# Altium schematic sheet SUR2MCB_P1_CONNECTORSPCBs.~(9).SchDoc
size 420 x 297 mm; Scale: 1:1; Разраб.: Иванов; Обозначение документа: АБВГ.123456.001 Э3; Пров.: Петров; Утв.: Сидоров; Наименование организации: ОАО "Концерн "МПО-Гидроприбор"; Перв. применение: АБВГ.123456.000; Наименование изделия 1: Плата; Наименование изделия 2: Схема электрическая; Наименование изделия 3: принципиальная; Нач. отд.: Нач. отд.; Фамилия нач. отд.: Сидоров
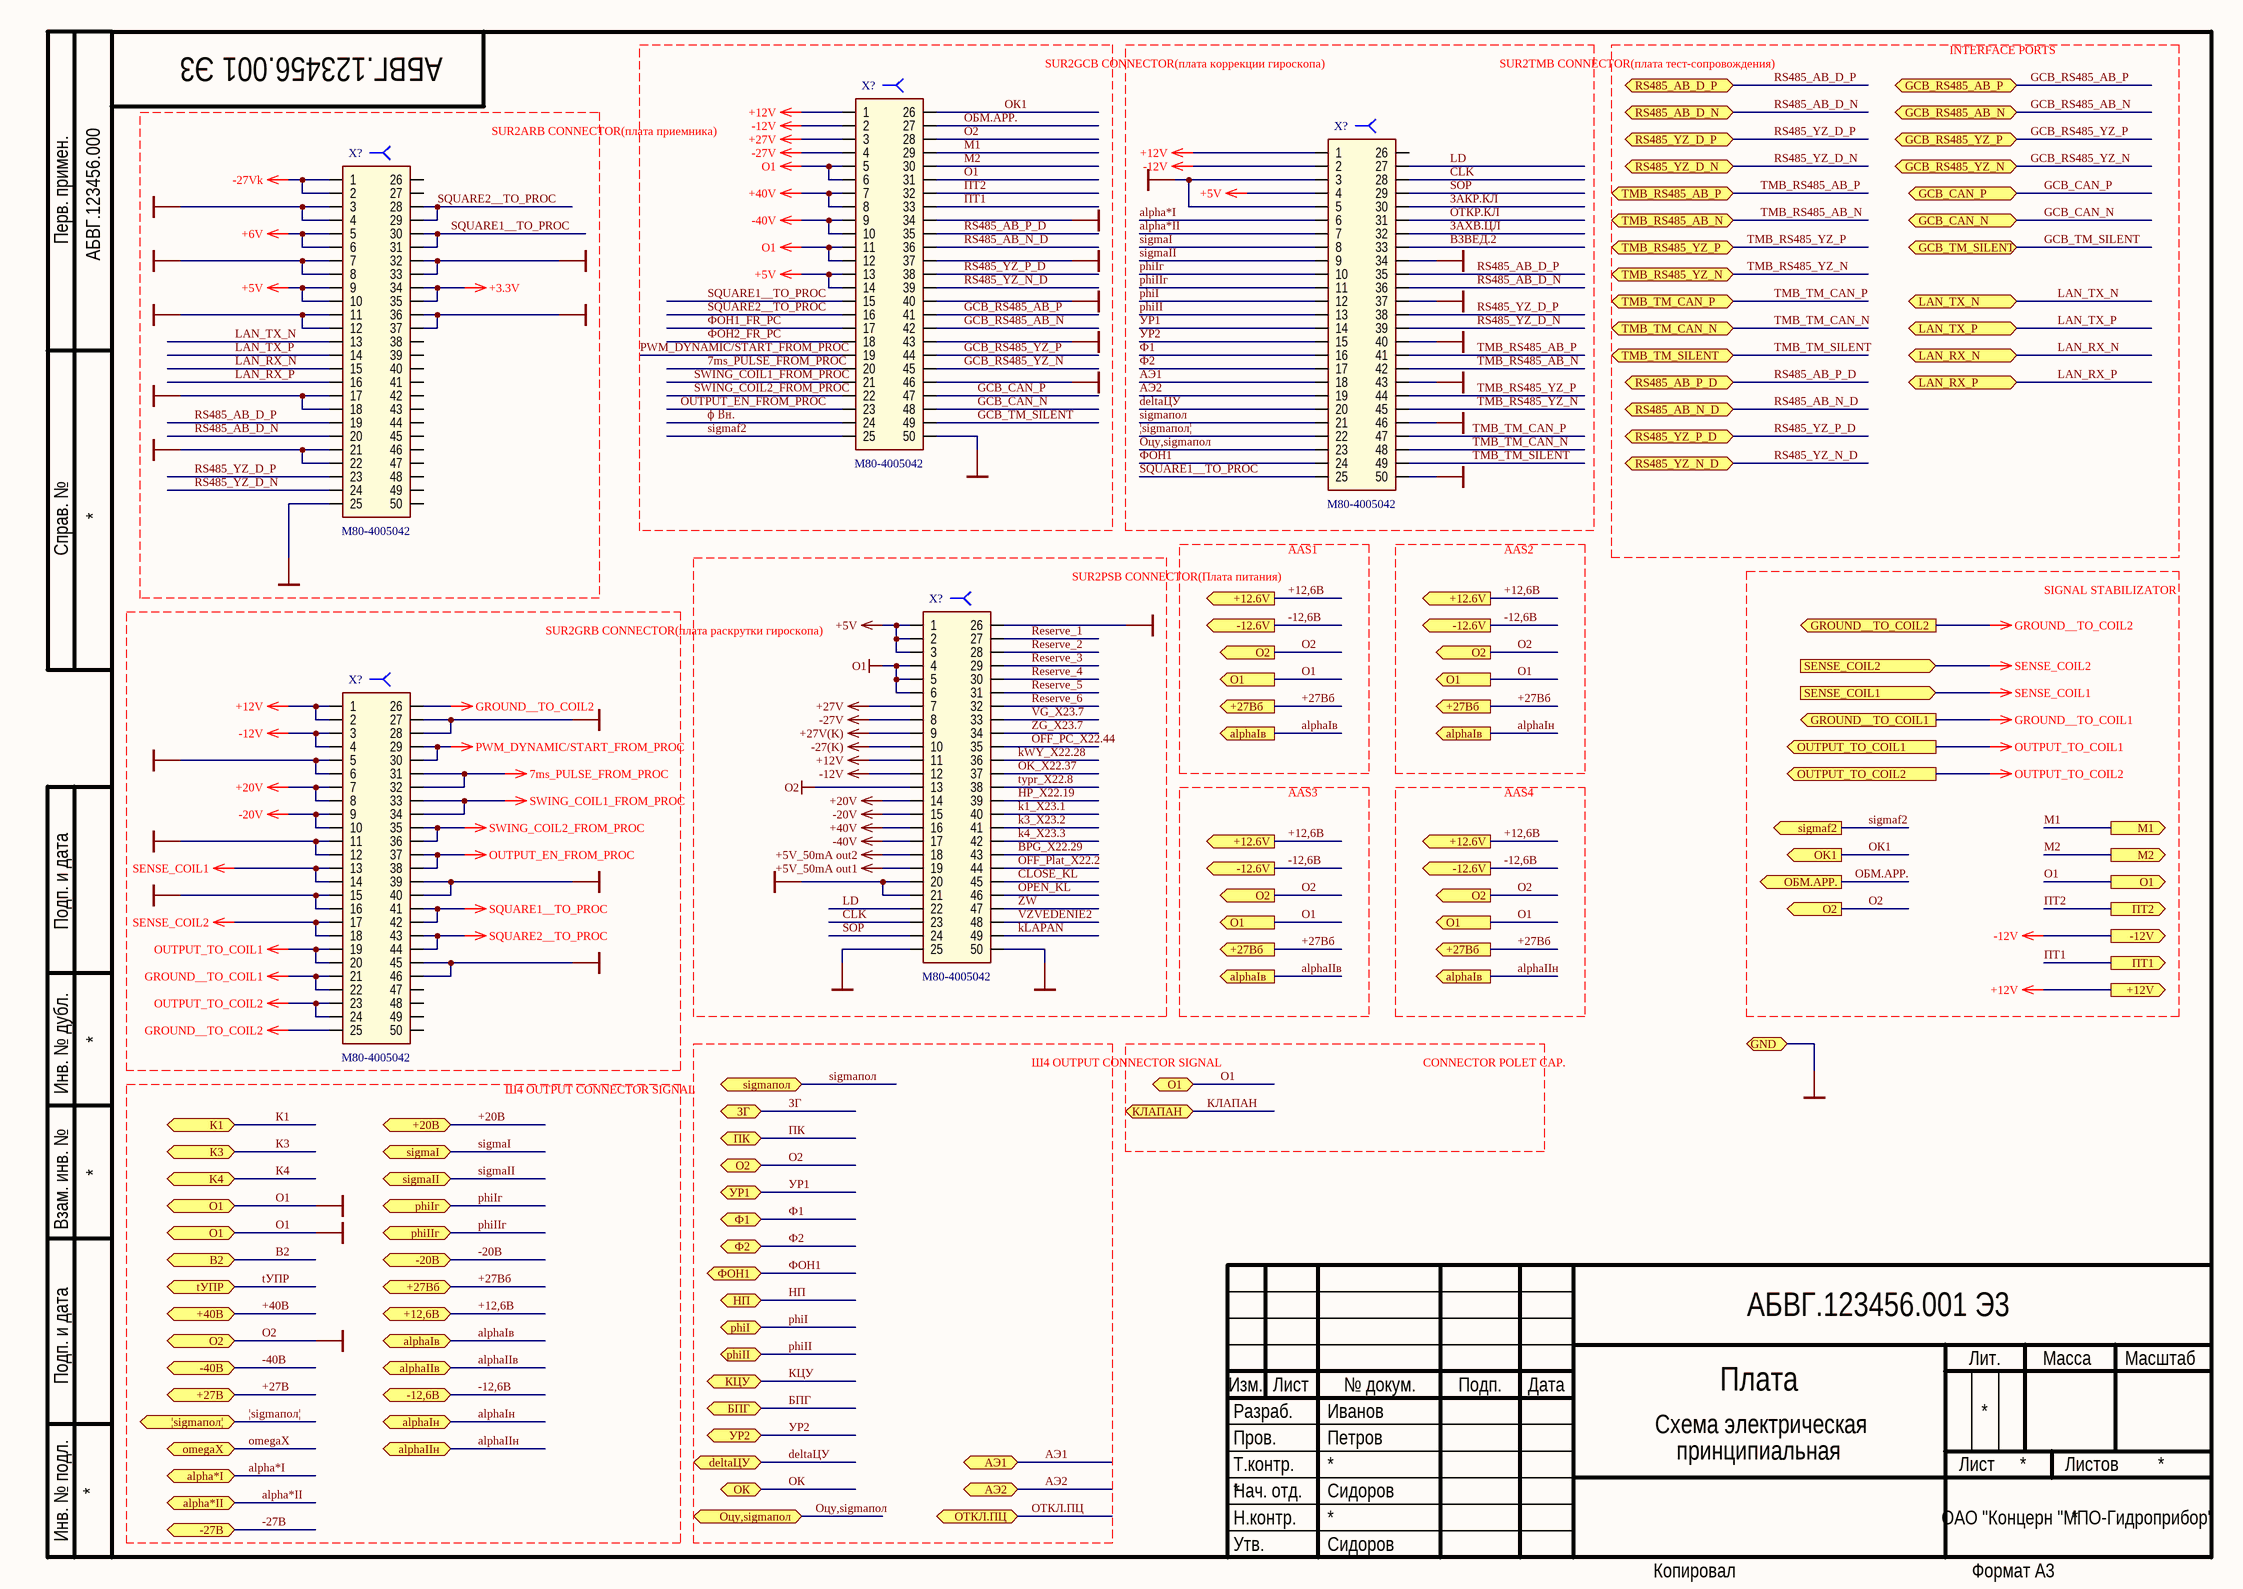
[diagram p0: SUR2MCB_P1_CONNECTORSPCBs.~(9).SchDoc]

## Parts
(Parts that share a designator on the sheet are numbered #1, #2 ... from top to bottom, then left to right.)
X?#1  value M80-4005042  [M80-4005042]
X?#2  value M80-4005042  [M80-4005042]
X?#3  value M80-4005042  [M80-4005042]
X?#4  value M80-4005042  [M80-4005042]
X?#5  value M80-4005042  [M80-4005042]

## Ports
+12,6В (bidir), +12.6V (out), +12V (out), +20В (bidir), +27В (bidir), +27Вб (bidir), +27Вб (out), +40В (bidir), -12,6В (bidir), -12.6V (out), -12V (out), -20В (bidir), -27В (bidir), -40В (bidir), alpha*I (bidir), alpha*II (bidir), alphaIIв (bidir), alphaIIн (bidir), alphaIв (bidir), alphaIв (out), alphaIн (bidir), B2 (bidir), deltaЦУ (bidir), GCB_CAN_N (bidir), GCB_CAN_P (bidir), GCB_RS485_AB_N (bidir), GCB_RS485_AB_P (bidir), GCB_RS485_YZ_N (bidir), GCB_RS485_YZ_P (bidir), GCB_TM_SILENT (bidir), GND (bidir), GROUND__TO_COIL1 (out), GROUND__TO_COIL2 (out), K4 (bidir), LAN_RX_N (bidir), LAN_RX_P (bidir), LAN_TX_N (bidir), LAN_TX_P (bidir), M1 (out), M2 (out), O1 (bidir), O1 (out), O2 (bidir), O2 (out), OK1 (out), omegaX (bidir), OUTPUT_TO_COIL1 (out), OUTPUT_TO_COIL2 (out), phiI (bidir), phiII (bidir), phiIIг (bidir), phiIг (bidir), RS485_AB_D_N (bidir), RS485_AB_D_P (bidir), RS485_AB_N_D (bidir), RS485_AB_P_D (bidir), RS485_YZ_D_N (bidir), RS485_YZ_D_P (bidir), RS485_YZ_N_D (bidir), RS485_YZ_P_D (bidir), SENSE_COIL1 (in), SENSE_COIL2 (in), sigmaf2 (out), sigmaI (bidir), sigmaII (bidir), sigmaпол (bidir), TMB_RS485_AB_N (bidir), TMB_RS485_AB_P (bidir), TMB_RS485_YZ_N (bidir), TMB_RS485_YZ_P (bidir), TMB_TM_CAN_N (bidir), TMB_TM_CAN_P (bidir), TMB_TM_SILENT (bidir), tУПР (bidir), ¦sigmaпол¦ (bidir), АЭ1 (bidir), АЭ2 (bidir), БПГ (bidir), ЗГ (bidir), К1 (bidir), К3 (bidir), КЛАПАН (bidir), КЦУ (bidir), НП (bidir), О1 (bidir), О2 (bidir), ОБМ.АРР. (out), ОК (bidir), ОТКЛ.ПЦ (bidir), Оцу,sigmaпол (bidir), ПК (bidir), ПТ1 (out), ПТ2 (out), УР1 (bidir), УР2 (bidir), Ф1 (bidir), Ф2 (bidir), ФОН1 (bidir)

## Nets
7ms_PULSE_FROM_PROC: X?#1.20 X?#5.31 X?#5.32
+3.3V: X?#3.34 X?#3.35
+5V: X?#1.13 X?#1.14 X?#2.4 X?#3.9 X?#3.10 X?#4.1 X?#4.2 X?#4.3
+5V_50mA out1: X?#4.19
+5V_50mA out2: X?#4.18
+6V: X?#3.5 X?#3.6
+12V: X?#1.1 X?#2.1 X?#4.11 X?#5.1 X?#5.2 ; port +12V
+20V: X?#4.14 X?#5.7 X?#5.8
+27V: X?#1.3 X?#4.7
+27V(K): X?#4.9
+40V: X?#1.7 X?#1.8 X?#4.16
-12V: X?#1.2 X?#2.2 X?#4.12 X?#5.3 X?#5.4 ; port -12V
-20V: X?#4.15 X?#5.9 X?#5.10
-27(K): X?#4.10
-27V: X?#1.4 X?#4.8
-27Vk: X?#3.1 X?#3.2
-40V: X?#1.9 X?#1.10 X?#4.17
GROUND__TO_COIL1: X?#5.21 X?#5.22 ; port GROUND__TO_COIL1
GROUND__TO_COIL2: X?#5.25 X?#5.26 ; port GROUND__TO_COIL2
OUTPUT_EN_FROM_PROC: X?#1.23 X?#5.37 X?#5.38
OUTPUT_TO_COIL1: X?#5.19 X?#5.20 ; port OUTPUT_TO_COIL1
OUTPUT_TO_COIL2: X?#5.23 X?#5.24 ; port OUTPUT_TO_COIL2
PWM_DYNAMIC/START_FROM_PROC: X?#1.19 X?#5.29 X?#5.30
SENSE_COIL1: X?#5.13 X?#5.14 ; port SENSE_COIL1
SENSE_COIL2: X?#5.17 X?#5.18 ; port SENSE_COIL2
SQUARE1__TO_PROC: X?#1.15 X?#2.25 X?#3.30 X?#3.31 X?#5.41 X?#5.42
SQUARE2__TO_PROC: X?#1.16 X?#3.28 X?#3.29 X?#5.43 X?#5.44
SWING_COIL1_FROM_PROC: X?#1.21 X?#5.33 X?#5.34
SWING_COIL2_FROM_PROC: X?#1.22 X?#5.35 X?#5.36
О1: X?#1.5 X?#1.6 X?#1.11 X?#1.12 X?#1.28 X?#1.31 X?#1.34 X?#1.37 X?#1.40 X?#1.43 X?#1.46 X?#1.50 X?#2.3 X?#2.5 X?#2.34 X?#2.37 X?#2.40 X?#2.43 X?#2.46 X?#2.50 X?#3.3 X?#3.4 X?#3.7 X?#3.8 X?#3.11 X?#3.12 X?#3.17 X?#3.18 X?#3.21 X?#3.22 X?#3.25 X?#3.32 X?#3.33 X?#3.36 X?#3.37 X?#4.4 X?#4.5 X?#4.6 X?#4.13 X?#4.20 X?#4.21 X?#4.25 X?#4.26 X?#4.50 X?#5.5 X?#5.6 X?#5.11 X?#5.12 X?#5.15 X?#5.16 X?#5.27 X?#5.28 X?#5.39 X?#5.40 X?#5.45 X?#5.46 ; port O1, port O2, port О2, port О1, port GND  [also labelled GND, О2]
+12,6В: port +12.6V, port +12,6В
-12,6В: port -12.6V, port -12,6В
alpha*I: X?#2.6 ; port alpha*I
alpha*II: X?#2.7 ; port alpha*II
alphaIIв: port alphaIв, port alphaIIв, port alphaIн, port alphaIIн  [also labelled alphaIIн, alphaIв, alphaIн]
BPG_X22.29: X?#4.43
CLK: X?#2.28 X?#4.23
CLOSE_KL: X?#4.45
deltaЦУ: X?#2.20 ; port deltaЦУ
GCB_CAN_N: X?#1.48 ; port GCB_CAN_N
GCB_CAN_P: X?#1.47 ; port GCB_CAN_P
GCB_RS485_AB_N: X?#1.42 ; port GCB_RS485_AB_N
GCB_RS485_AB_P: X?#1.41 ; port GCB_RS485_AB_P
GCB_RS485_YZ_N: X?#1.45 ; port GCB_RS485_YZ_N
GCB_RS485_YZ_P: X?#1.44 ; port GCB_RS485_YZ_P
GCB_TM_SILENT: X?#1.49 ; port GCB_TM_SILENT
HP_X22.19: X?#4.39
k1_X23.1: X?#4.40
k3_X23.2: X?#4.41
k4_X23.3: X?#4.42
kLAPAN: X?#4.49
kWY_X22.28: X?#4.36
LAN_RX_N: X?#3.15 ; port LAN_RX_N
LAN_RX_P: X?#3.16 ; port LAN_RX_P
LAN_TX_N: X?#3.13 ; port LAN_TX_N
LAN_TX_P: X?#3.14 ; port LAN_TX_P
LD: X?#2.27 X?#4.22
OFF_PC_X22.44: X?#4.35
OFF_Plat_X22.2: X?#4.44
OK_X22.37: X?#4.37
OPEN_KL: X?#4.46
phiI: X?#2.12 ; port phiI
phiII: X?#2.13 ; port phiII
phiIIг: X?#2.11 ; port phiIIг
phiIг: X?#2.10 ; port phiIг
Reserve_1: X?#4.27
Reserve_2: X?#4.28
Reserve_3: X?#4.29
Reserve_4: X?#4.30
Reserve_5: X?#4.31
Reserve_6: X?#4.32
RS485_AB_D_N: X?#2.36 X?#3.20 ; port RS485_AB_D_N
RS485_AB_D_P: X?#2.35 X?#3.19 ; port RS485_AB_D_P
RS485_AB_N_D: X?#1.36 ; port RS485_AB_N_D
RS485_AB_P_D: X?#1.35 ; port RS485_AB_P_D
RS485_YZ_D_N: X?#2.39 X?#3.24 ; port RS485_YZ_D_N
RS485_YZ_D_P: X?#2.38 X?#3.23 ; port RS485_YZ_D_P
RS485_YZ_N_D: X?#1.39 ; port RS485_YZ_N_D
RS485_YZ_P_D: X?#1.38 ; port RS485_YZ_P_D
sigmaf2: X?#1.25 ; port sigmaf2
sigmaI: X?#2.8 ; port sigmaI
sigmaII: X?#2.9 ; port sigmaII
sigmaпол: X?#2.21 ; port sigmaпол
SOP: X?#2.29 X?#4.24
TMB_RS485_AB_N: X?#2.42 ; port TMB_RS485_AB_N
TMB_RS485_AB_P: X?#2.41 ; port TMB_RS485_AB_P
TMB_RS485_YZ_N: X?#2.45 ; port TMB_RS485_YZ_N
TMB_RS485_YZ_P: X?#2.44 ; port TMB_RS485_YZ_P
TMB_TM_CAN_N: X?#2.48 ; port TMB_TM_CAN_N
TMB_TM_CAN_P: X?#2.47 ; port TMB_TM_CAN_P
TMB_TM_SILENT: X?#2.49 ; port TMB_TM_SILENT
typr_X22.8: X?#4.38
VG_X23.7: X?#4.33
VZVEDENIE2: X?#4.48
ZG_X23.7: X?#4.34
ZW: X?#4.47
¦sigmaпол¦: X?#2.22 ; port ¦sigmaпол¦
ϕ Вн.: X?#1.24
АЭ1: X?#2.18 ; port АЭ1
АЭ2: X?#2.19 ; port АЭ2
ВЗВЕД.2: X?#2.33
ЗАКР.КЛ: X?#2.30
ЗАХВ.ЦЛ: X?#2.32
М1: X?#1.29 ; port M1
М2: X?#1.30 ; port M2
ОБМ.АРР.: X?#1.27 ; port ОБМ.АРР.
ОК1: X?#1.26 ; port OK1
ОТКР.КЛ: X?#2.31
Оцу,sigmaпол: X?#2.23 ; port Оцу,sigmaпол
ПТ1: X?#1.33 ; port ПТ1
ПТ2: X?#1.32 ; port ПТ2
УР1: X?#2.14 ; port УР1
УР2: X?#2.15 ; port УР2
Ф1: X?#2.16 ; port Ф1
Ф2: X?#2.17 ; port Ф2
ФОН1: X?#2.24 ; port ФОН1
ФОН1_FR_PC: X?#1.17
ФОН2_FR_PC: X?#1.18

Not connected (* = marked no-connect by the designer): X?#2 26; X?#3 26 27 38 39 40 41 42 43 44 45 46 47 48 49 50; X?#5 47 48 49 50

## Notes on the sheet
- INTERFACE PORTS
- (near X?#1) SUR2GCB CONNECTOR(плата коррекции гироскопа)
- SUR2TMB CONNECTOR(плата тест-сопровождения)
- (near X?#3) SUR2ARB CONNECTOR(плата приемника)
- (near X?#4) SUR2PSB CONNECTOR(Плата питания)
- AAS1
- AAS2
- SIGNAL STABILIZATOR
- SUR2GRB CONNECTOR(плата раскрутки гироскопа)
- AAS3
- AAS4
- Ш4 OUTPUT CONNECTOR SIGNAL
- CONNECTOR POLET CAP.

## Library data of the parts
X?#1-X?#5 = M80-4005042: 25+25 WAY FEMALE PC TAIL 3MM; ValueManufacturer: Harwin Inc.; PowerVoltage: 120V; TechSpec: 3A; ValueDescription: M80-4005042 Розетка Harwin Inc.  5.55x60mm  3A; ValueType: Female Socket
